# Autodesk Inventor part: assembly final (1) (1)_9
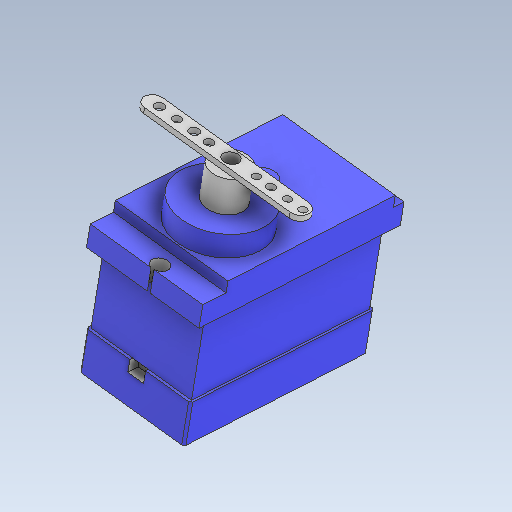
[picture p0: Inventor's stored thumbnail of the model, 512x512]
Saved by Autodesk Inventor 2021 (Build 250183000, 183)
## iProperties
Created: 2021-07
Part Number: assembly final (1) (1)_9
Material: Generic
Document SubType Name: Modeling
Designer: TARUN
Density: 1 g/cm^3
Appearance: Default
Author: TARUN
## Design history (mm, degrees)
feature "Base1"
body "Solid1"
